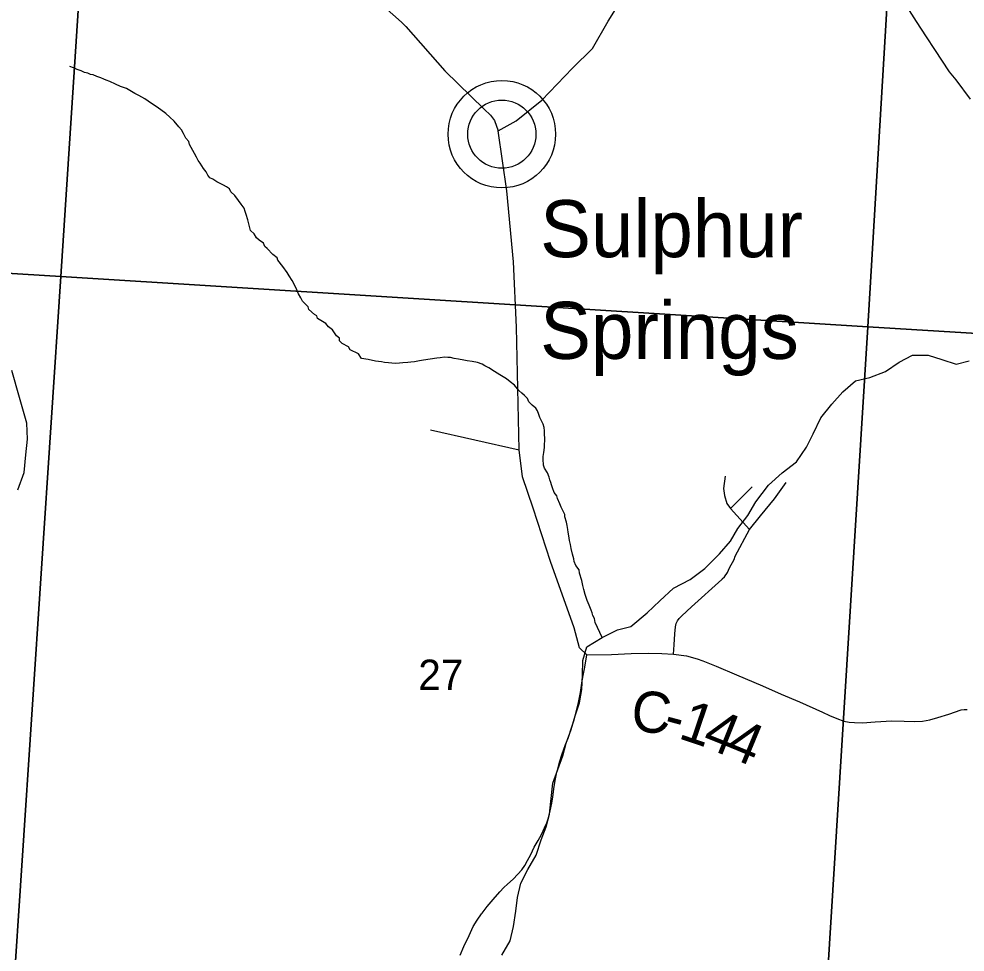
# Model space of a CAD drawing. Extents: x 0 to 45.4, y -2.2 to 22.
# Drawn here: x 5.991 to 7.301, y 16.232 to 17.524 of the extents above; entities that cross this region are included whole.
import ezdxf

# ---------------------------------------------------------------- set-up
doc = ezdxf.new("R2010")
doc.units = 0
for name, color, linetype in [('GM_X_Corporation', 7, 'Continuous'), ('GM_X_County_Road', 7, 'Continuous'), ('GM_X_County_Road_Text', 7, 'Continuous'), ('GM_X_Minor_River', 7, 'Continuous'), ('GM_X_Section_Text', 7, 'Continuous'), ('GM_X_Township_Road', 7, 'Continuous'), ('GM_X_Unincorporated', 7, 'Continuous'), ('GM_X_Unincorporated_Location', 7, 'Continuous'), ('GM_X_Unincorporated_Text', 7, 'Continuous')]:
    doc.layers.add(name, color=color, linetype=linetype)

msp = doc.modelspace()

# ---------------------------------------------------------------- linework, layer by layer
at = {"layer": 'GM_X_Corporation'}
for points in [[(5.0121, 18.2353), (6.1142, 18.166), (6.0488, 17.1677), (4.9524, 17.2347)], [(6.1142, 18.166), (7.2262, 18.1039), (7.1661, 17.098), (6.0488, 17.1677)], [(7.2262, 18.1039), (8.3245, 18.0384), (8.2701, 17.0306), (7.1661, 17.098)], [(6.0488, 17.1677), (5.9818, 16.1569), (4.8941, 16.2254), (4.9524, 17.2347)], [(7.1661, 17.098), (7.1036, 16.0876), (5.9818, 16.1569), (6.0488, 17.1677)], [(8.2701, 17.0306), (8.2164, 16.0186), (7.1036, 16.0876), (7.1661, 17.098)]]:
    msp.add_lwpolyline(points, close=True, dxfattribs=at)
at = {"layer": 'GM_X_County_Road'}
for points in [[(7.3085, 17.4131), (7.2883, 17.4399), (7.2792, 17.4506), (7.2589, 17.4816), (7.2475, 17.4993), (7.2335, 17.5206), (7.2132, 17.5527), (7.1949, 17.5781), (7.1795, 17.5964), (7.166, 17.6277), (7.1453, 17.6629), (7.1275, 17.6925), (7.1195, 17.7075), (7.114, 17.7227), (7.1102, 17.7411), (7.1078, 17.7635), (7.1067, 17.7735), (7.1058, 17.7799), (7.1008, 17.7934)], [(6.4847, 17.5519), (6.5204, 17.5195), (6.5268, 17.5136), (6.5805, 17.4523), (6.6352, 17.3992), (6.6436, 17.391), (6.6494, 17.3833), (6.6546, 17.3691), (6.6793, 17.383), (6.7147, 17.4114), (6.7572, 17.4557), (6.7852, 17.4833), (6.8065, 17.5212), (6.8214, 17.5447)], [(6.602, 16.228), (6.6071, 16.24), (6.6142, 16.255), (6.62, 16.2677), (6.6252, 16.2764), (6.6313, 16.285), (6.6321, 16.2858), (6.6393, 16.2952), (6.6476, 16.3049), (6.6569, 16.3156), (6.6624, 16.3214), (6.6674, 16.3261), (6.6751, 16.3333), (6.6818, 16.3402), (6.6872, 16.3461), (6.6915, 16.3522), (6.6949, 16.3587), (6.6995, 16.3673), (6.7042, 16.3772), (6.7097, 16.3868), (6.7142, 16.3951), (6.7187, 16.4043), (6.722, 16.4112), (6.7243, 16.4181), (6.7263, 16.4278), (6.7289, 16.4381), (6.7301, 16.4471), (6.732, 16.4614), (6.734, 16.4722), (6.7358, 16.481), (6.7369, 16.4856), (6.7395, 16.4951), (6.7429, 16.5066), (6.7475, 16.5196), (6.7511, 16.5284), (6.7562, 16.5439), (6.759, 16.5525), (6.7633, 16.5679), (6.7654, 16.5775), (6.7683, 16.5914), (6.7708, 16.6077), (6.7725, 16.6174), (6.7742, 16.6266), (6.7771, 16.6437), (6.7671, 16.6535), (6.7595, 16.6812), (6.7269, 16.7729), (6.7027, 16.8466), (6.6879, 16.8903), (6.6833, 16.9276), (6.6796, 17.0971), (6.6758, 17.1879), (6.6663, 17.2859), (6.6546, 17.3691)], [(6.7771, 16.6437), (6.8112, 16.6442), (6.8386, 16.6455), (6.8624, 16.6459), (6.881, 16.6455), (6.8973, 16.6447), (6.9152, 16.6421), (6.9301, 16.6383), (6.9379, 16.6355), (6.9564, 16.6282), (6.9844, 16.6162), (7.0205, 16.6009), (7.0461, 16.5893), (7.0714, 16.5785), (7.1032, 16.5641), (7.1129, 16.5598), (7.1234, 16.5553), (7.133, 16.552), (7.1404, 16.5505), (7.1478, 16.5499), (7.1586, 16.5497), (7.1765, 16.5511), (7.1992, 16.5521), (7.2165, 16.5516), (7.2308, 16.5512), (7.2417, 16.5518), (7.2518, 16.5537), (7.263, 16.5568), (7.2782, 16.5616), (7.2953, 16.5674), (7.2994, 16.5679), (7.3037, 16.5679)]]:
    msp.add_lwpolyline(points, dxfattribs=at)
at = {"layer": 'GM_X_Minor_River'}
for points in [[(6.4349, 17.0782), (6.4346, 17.082), (6.4305, 17.0851), (6.4279, 17.0897), (6.4249, 17.0935), (6.4197, 17.0978), (6.4156, 17.1024), (6.4044, 17.1095), (6.4033, 17.1129), (6.3999, 17.1149), (6.3921, 17.1218), (6.3914, 17.1253), (6.3836, 17.1334), (6.381, 17.138), (6.3781, 17.1434), (6.3744, 17.1522), (6.3693, 17.1618), (6.3652, 17.1683), (6.3623, 17.1729), (6.3564, 17.1814), (6.3493, 17.1899), (6.3486, 17.1933), (6.3423, 17.198), (6.3348, 17.2061), (6.3315, 17.2088), (6.3293, 17.2138), (6.3237, 17.218), (6.32, 17.2208), (6.3166, 17.2265), (6.3114, 17.2312), (6.3097, 17.2384), (6.3079, 17.246), (6.3057, 17.2533), (6.3043, 17.2575), (6.3029, 17.2621), (6.2984, 17.2675), (6.2947, 17.2725), (6.2899, 17.2794), (6.2843, 17.2848), (6.2825, 17.289), (6.2784, 17.2918), (6.2743, 17.2937), (6.2649, 17.2985), (6.2596, 17.302), (6.2551, 17.3039), (6.2525, 17.3078), (6.25, 17.3124), (6.2463, 17.317), (6.2418, 17.3243), (6.2393, 17.3282), (6.2367, 17.3328), (6.2341, 17.3377), (6.2271, 17.35), (6.2261, 17.3542), (6.222, 17.3592), (6.2187, 17.3654), (6.2158, 17.3704), (6.2124, 17.3746), (6.2057, 17.3823), (6.1998, 17.3881), (6.1942, 17.3931), (6.1875, 17.3982), (6.1807, 17.4029), (6.1744, 17.4072), (6.1654, 17.4134), (6.1571, 17.4181), (6.1515, 17.4208), (6.1444, 17.4248), (6.1399, 17.4279), (6.1316, 17.4307), (6.1248, 17.4338), (6.1166, 17.4374), (6.1117, 17.4394), (6.1083, 17.4409), (6.1045, 17.4425), (6.0989, 17.4445), (6.0936, 17.4465), (6.0902, 17.4473), (6.0861, 17.4489), (6.0819, 17.4501), (6.077, 17.4521), (6.0714, 17.4541), (6.0665, 17.4565), (6.0616, 17.4581)], [(6.7985, 16.6678), (6.7887, 16.6885), (6.788, 16.6942), (6.7854, 16.6981), (6.7847, 16.7019), (6.7833, 16.7057), (6.7804, 16.7126), (6.7775, 16.7188), (6.7749, 16.7272), (6.7732, 16.734), (6.7718, 16.7398), (6.7704, 16.7466), (6.7671, 16.7566), (6.7664, 16.7612), (6.762, 16.7673), (6.7595, 16.7727), (6.7591, 16.7765), (6.7574, 16.783), (6.7556, 16.791), (6.7546, 16.7964), (6.7531, 16.8021), (6.7521, 16.8082), (6.7515, 16.8135), (6.7508, 16.817), (6.7501, 16.8227), (6.749, 16.8273), (6.7469, 16.8345), (6.7466, 16.8379), (6.7433, 16.8445), (6.7418, 16.8479), (6.7396, 16.8525), (6.7364, 16.8602), (6.7357, 16.8636), (6.732, 16.8686), (6.7294, 16.8747), (6.7284, 16.8789), (6.7273, 16.8824), (6.7258, 16.8858), (6.7251, 16.8896), (6.7226, 16.8958), (6.7185, 16.9019), (6.7171, 16.9061), (6.7165, 16.9145), (6.7165, 16.9183), (6.7174, 16.924), (6.7186, 16.9308), (6.7189, 16.9445), (6.7186, 16.9479), (6.7187, 16.954), (6.718, 16.9586), (6.7169, 16.9632), (6.7122, 16.9724), (6.7107, 16.9766), (6.7089, 16.9816), (6.7067, 16.985), (6.7015, 16.9893), (6.697, 16.9939), (6.6948, 16.9985), (6.6907, 17.0028), (6.687, 17.0059), (6.6829, 17.0098), (6.677, 17.0171), (6.671, 17.0217), (6.6661, 17.0256), (6.6568, 17.0311), (6.6493, 17.0358), (6.6414, 17.0409), (6.6358, 17.044), (6.6324, 17.046), (6.626, 17.0484), (6.6185, 17.05), (6.6117, 17.0505), (6.6071, 17.0517), (6.5996, 17.053), (6.5935, 17.0538), (6.5883, 17.0551), (6.5845, 17.0555), (6.5799, 17.0556), (6.5742, 17.0549), (6.5697, 17.0546), (6.5602, 17.0529), (6.5511, 17.0515), (6.5454, 17.0505), (6.5385, 17.0494), (6.5336, 17.0488), (6.5294, 17.0485), (6.5222, 17.0478), (6.518, 17.0475), (6.5127, 17.0472), (6.5071, 17.0473), (6.5025, 17.0481), (6.4969, 17.0486), (6.4931, 17.0491), (6.4844, 17.0503), (6.4742, 17.0524), (6.4651, 17.0541), (6.4611, 17.0606), (6.4494, 17.0661), (6.4472, 17.07), (6.4386, 17.0747), (6.4349, 17.0782)], [(6.7609, 16.5592), (6.7671, 16.5774), (6.7702, 16.5957), (6.771, 16.6154), (6.7718, 16.636), (6.7772, 16.6549), (6.7985, 16.6678), (6.8197, 16.6784), (6.8379, 16.6829), (6.8607, 16.7018), (6.8782, 16.7185), (6.8972, 16.7359), (6.92, 16.748), (6.9405, 16.7631), (6.961, 16.7836), (6.9762, 16.801), (6.9861, 16.8185), (6.9999, 16.8367), (7.0113, 16.8556), (7.0288, 16.8784), (7.0478, 16.8958), (7.0676, 16.9109), (7.0813, 16.9314), (7.0904, 16.9496), (7.1011, 16.9717), (7.1163, 16.9906), (7.1316, 17.008), (7.149, 17.0232), (7.1688, 17.0277), (7.1908, 17.036), (7.2097, 17.0488), (7.228, 17.0586), (7.2499, 17.0586), (7.2688, 17.0524), (7.2885, 17.0463), (7.3067, 17.0508)], [(6.6596, 16.228), (6.6711, 16.2477), (6.6757, 16.2675), (6.6788, 16.2887), (6.6812, 16.3078), (6.6858, 16.3275), (6.6957, 16.3465), (6.7072, 16.3662), (6.7141, 16.3875), (6.7209, 16.4057), (6.7256, 16.4232), (6.7271, 16.4407), (6.7303, 16.4658), (6.7441, 16.5037), (6.7487, 16.5212), (6.7556, 16.5402), (6.7609, 16.5592)]]:
    msp.add_lwpolyline(points, dxfattribs=at)
at = {"layer": 'GM_X_Township_Road'}
for p, q in [((6.5607, 16.9552), (6.6833, 16.9276)), ((6.976, 16.8463), (7.0062, 16.8762))]:
    msp.add_line(p, q, dxfattribs=at)
for points in [[(5.9896, 16.8723), (5.9982, 16.896), (6.0005, 16.9207), (6.0028, 16.9422), (6.0019, 16.9642), (5.9918, 16.9998), (5.9809, 17.0373)], [(6.9687, 16.891), (6.9666, 16.874), (6.9679, 16.8644), (6.9708, 16.8534), (6.976, 16.8463), (7.0025, 16.8174)], [(6.9639, 16.7481), (6.9647, 16.7489), (6.9679, 16.7518), (6.9718, 16.7578), (6.9746, 16.7639), (6.9811, 16.7756), (6.9825, 16.7804), (7.0025, 16.8174), (7.0175, 16.836), (7.0371, 16.8597), (7.0533, 16.8822)], [(6.8973, 16.6447), (6.8982, 16.6575), (6.8992, 16.6729), (6.9, 16.6824), (6.9009, 16.6869), (6.9027, 16.6907), (6.9051, 16.6938), (6.9086, 16.6975), (6.9221, 16.7099), (6.9639, 16.7481)]]:
    msp.add_lwpolyline(points, dxfattribs=at)
at = {"layer": 'GM_X_Unincorporated'}
for radius in [0.0744, 0.0472]:
    msp.add_circle((6.6595, 17.3645), radius, dxfattribs=at)
at = {"layer": 'GM_X_Unincorporated_Location'}
msp.add_line((6.6595, 17.3645), (6.6595, 17.3645), dxfattribs=at)

# ---------------------------------------------------------------- texts
at = {"layer": 'GM_X_County_Road_Text'}
for s, rotation, p in [('C', 353.7827, (6.8365, 16.5391)), ('1', 341.2684, (6.9022, 16.5288)), ('-', 344.9773, (6.8806, 16.5345)), ('4', 338.2098, (6.9346, 16.5178)), ('4', 337.4714, (6.9669, 16.5049))]:
    msp.add_text(s, height=0.0568, rotation=rotation, dxfattribs=at).set_placement(p)
at = {"layer": 'GM_X_Section_Text'}
msp.add_text('27', height=0.04186, rotation=0, dxfattribs=at).set_placement((6.5438, 16.5952))
at = {"layer": 'GM_X_Unincorporated_Text'}
for s, p in [('Sulphur', (6.7125, 17.1942)), ('Springs', (6.7125, 17.0534))]:
    msp.add_text(s, height=0.07898, rotation=0, dxfattribs=at).set_placement(p)

doc.saveas('drawing.dxf')
